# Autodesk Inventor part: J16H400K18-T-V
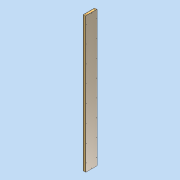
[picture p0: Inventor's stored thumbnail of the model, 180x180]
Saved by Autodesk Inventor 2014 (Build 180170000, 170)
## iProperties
Created: 2012-06
Part Number: J16H400K18-T-V
Document SubType Name: Modeling
Designer: david.appleford
Mass: 165032 g
Surface Area: 137565 cm^2
Volume: 165032 cm^3
Density: 1 g/cm^3
Description: Joist 4w x 400mm 18 Locks - 80mm
Cost Center: £320.00
Material: Generic
Appearance: Default
Justset: False
Author: david.appleford
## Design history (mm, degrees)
sketch "Sketch1"
  geometry: L1 (86, 0)-(86, 400); L2 (0, 400)-(0, 0); L3 (9.1, 356)-(76.9, 356); L4 (77, 400)-(77, 0); L5 (76.9, 44)-(9.1, 44); L6 (9, 0)-(9, 400); L7 (76.9, 355.9)-(9.1, 355.9); L8 (9.1, 44.1)-(76.9, 44.1); L9 (9.1, 400)-(9.1, 356); L10 (76.9, 356)-(76.9, 400); L11 (9.1, 355.9)-(9.1, 44.1); L12 (9.1, 44)-(9.1, 0); L13 (76.9, 0)-(76.9, 44); L14 (76.9, 44.1)-(76.9, 355.9); L15 (0, 0)-(9, 0); L16 (9.1, 0)-(76.9, 0); L17 (77, 0)-(86, 0); L18 (9, 400)-(0, 400); L19 (86, 400)-(77, 400); L20 (76.9, 400)-(9.1, 400)
  constraints: 40 end point, 22 parallel, 8 collinear, 7 perpendicular, 4 horizontal
  dimensions: "d1" = 86 distance between parallel lines of L1 L2; "d4" = 9 distance between parallel lines of L6 L2; "d5" = 9 distance between parallel lines of L1 L4; "d6" = 0.1 distance between parallel lines of L7 L3; "d7" = 0.1 distance between parallel lines of L9 L6; "d8" = 0.1 distance between parallel lines of L4 L10; "d9" = 0.1 distance between parallel lines of L5 L8; "d10" = 400 distance between parallel lines of L15 L18; "d11" = 44 distance between parallel lines of L3 L19; "d13" = 44 distance between parallel lines of L17 L5
extrude "Extrusion1" new body sketch "Sketch1" distance "d14" = 4812; taper "d15" = 0 deg
sketch "Sketch2" dims "d26" = 10
  geometry: L1 (0, 400)-(-4812, 400) reference; L2 (0, 0)-(-4812, 0) reference; L3 (34, 560.068)-(34, -205.63); L4 (-4846, 560.068)-(-4846, -205.63); L5 (0, 400)-(0, 0) reference; L6 (-4812, 400)-(-4812, 0) reference; 18 further points
  constraints: 4 end point, 1 horizontal, 1 horizontal alignment, 1 vertical alignment, 14 other
  dimensions: "d16" = 28 distance from line of L1 point (-271, 372); "d17" = 28 distance from line of L2 point (-271, 28) (= d16); "d18" = 34 distance between parallel lines of L5 L3; "d19" = 4880 distance between parallel lines of L4 L3; "d20" = 305 distance from line of point (-271, 372) L3; "d23" = 610 distance of point (-271, 372) point (-881, 372); "d35" = 28 distance from line of point (-4784, 200) L6 (= d16); "d36" = 28 distance from line of point (-28, 200) L5 (= d16); "d37" = 200 distance from line of point (-4784, 200) L1 (= 0.5 x d38); "d38" = 400 distance between parallel lines of L2 L1 (derived)
hole "Hole1" sketch "Sketch2" at (-271, 28), (-271, 372), (-881, 372), (-881, 28), (-1491, 372), (-1491, 28), (-2101, 372), (-2101, 28), (-2711, 372), (-2711, 28), (-3321, 372), (-3321, 28)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 diameter "d28" = 13; stored, may be unused: countersink angle "d32" = 90 deg, drill point angle "d34" = 118 deg; dims "d29" = 6, "d30" = 4, "d31" = 2, "d33" = 20
body "Solid1"
other parameters: "d0" = 397, "d2" = 44, "d3" = 44
